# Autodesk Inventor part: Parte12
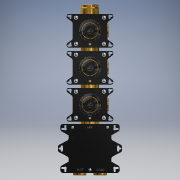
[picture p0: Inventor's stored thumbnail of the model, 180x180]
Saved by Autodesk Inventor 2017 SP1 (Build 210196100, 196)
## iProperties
Created: 2021-08
Part Number: Parte12
Material: Generico
Document SubType Name: Modeling
Designer: ROSSETTO
Density: 1 g/cm^3
Appearance: Default
Author: ROSSETTO
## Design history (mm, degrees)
feature "Base2"
node "Solido1"
node "Solido3"
